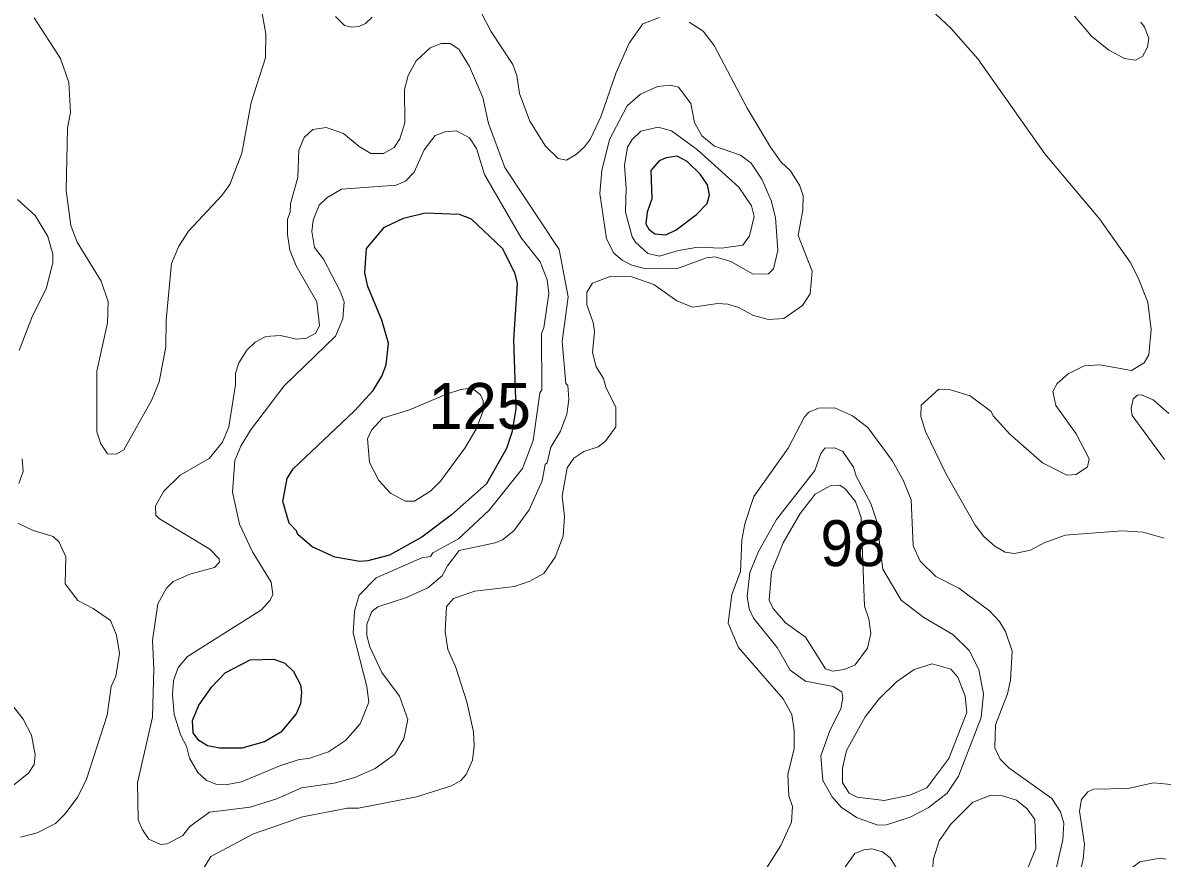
# Model space of a CAD drawing. Extents: x 673.6 to 698.9, y 7012 to 7040.1.
# Drawn here: x 688.765 to 690.749, y 7022.844 to 7024.299 of the extents above; entities that cross this region are included whole.
import ezdxf

# ---------------------------------------------------------------- set-up
doc = ezdxf.new("R2010")
doc.units = 0
doc.header["$LTSCALE"] = 0.032
doc.layers.add('1', color=7, linetype='Continuous', lineweight=25)
doc.layers.add('2', color=7, linetype='Continuous', lineweight=13)
doc.layers.add('21', color=7, linetype='Continuous')

msp = doc.modelspace()

# ---------------------------------------------------------------- linework, layer by layer
at = {"layer": '1'}
for points in [[(689.9221, 7024.0578), (689.9046, 7024.0666), (689.8854, 7024.0641), (689.8734, 7024.0589), (689.859, 7024.0419), (689.8603, 7023.9927), (689.8522, 7023.9692), (689.8499, 7023.9488), (689.8551, 7023.9395), (689.8655, 7023.9317), (689.885, 7023.9296), (689.9029, 7023.9383), (689.938, 7023.965), (689.9567, 7023.9845), (689.9607, 7023.9995), (689.9575, 7024.0169), (689.9444, 7024.0353)], [(689.6234, 7023.6258), (689.6166, 7023.5856), (689.6073, 7023.5576), (689.5728, 7023.4958), (689.5119, 7023.4422), (689.46, 7023.4028), (689.4039, 7023.3716), (689.3657, 7023.3616), (689.3522, 7023.3609), (689.3082, 7023.3682), (689.2689, 7023.386), (689.2442, 7023.4074), (689.2419, 7023.4139), (689.2292, 7023.4277), (689.2179, 7023.4651), (689.2252, 7023.5054), (689.2362, 7023.522), (689.343, 7023.6231), (689.375, 7023.6583), (689.3902, 7023.6834), (689.3978, 7023.7034), (689.4019, 7023.7413), (689.3903, 7023.781), (689.3659, 7023.8395), (689.3608, 7023.8637), (689.3636, 7023.9058), (689.3948, 7023.9434), (689.4282, 7023.9589), (689.466, 7023.968), (689.5252, 7023.9655), (689.5457, 7023.9575), (689.5999, 7023.9063), (689.6212, 7023.8644), (689.6262, 7023.8447), (689.6197, 7023.747)], [(689.2502, 7023.1332), (689.2488, 7023.1126), (689.2414, 7023.095), (689.2145, 7023.0633), (689.1862, 7023.0467), (689.1467, 7023.0353), (689.1081, 7023.0353), (689.0867, 7023.0394), (689.0716, 7023.0485), (689.0617, 7023.062), (689.0605, 7023.0839), (689.0716, 7023.1101), (689.0943, 7023.1422), (689.1176, 7023.1667), (689.1611, 7023.1895), (689.2021, 7023.1906), (689.2214, 7023.1837), (689.2367, 7023.1692), (689.2488, 7023.1456)]]:
    msp.add_lwpolyline(points, close=True, dxfattribs=at)
at = {"layer": '2'}
for points in [[(688.7852, 7024.3077), (688.831, 7024.2372), (688.8455, 7024.1952), (688.8481, 7024.1428), (688.8432, 7024.1163), (688.8406, 7024.0069), (688.8487, 7023.9461), (688.8597, 7023.9167), (688.9014, 7023.8488), (688.9138, 7023.8132), (688.9128, 7023.7767), (688.8941, 7023.6922), (688.8941, 7023.5868), (688.9011, 7023.5658), (688.9126, 7023.5481), (688.9279, 7023.5474), (688.941, 7023.5549), (688.9894, 7023.6409), (689.0024, 7023.6735), (689.014, 7023.7347), (689.0149, 7023.7809), (689.024, 7023.8797), (689.0369, 7023.9102), (689.0535, 7023.9359), (689.1118, 7023.9983), (689.1254, 7024.0176), (689.1467, 7024.0722), (689.1628, 7024.1603), (689.1875, 7024.2382), (689.1882, 7024.2802), (689.1801, 7024.325)], [(689.3099, 7024.3099), (689.3255, 7024.2947), (689.3382, 7024.2913), (689.3503, 7024.2925), (689.362, 7024.2981), (689.3737, 7024.3088)], [(689.5646, 7024.3149), (689.5804, 7024.2848), (689.6187, 7024.2263), (689.6254, 7024.2076), (689.6302, 7024.1758), (689.6481, 7024.1279), (689.6751, 7024.0844), (689.6974, 7024.0625), (689.7117, 7024.0601), (689.7296, 7024.0701), (689.7435, 7024.0828), (689.7535, 7024.0972), (689.7716, 7024.1353), (689.7985, 7024.2128), (689.8209, 7024.2635), (689.8449, 7024.2973), (689.8739, 7024.3083)], [(690.7529, 7023.401), (690.7158, 7023.4115), (690.6793, 7023.4141), (690.5804, 7023.4067), (690.5435, 7023.3932), (690.5198, 7023.3806), (690.4919, 7023.3748), (690.4756, 7023.3771), (690.458, 7023.3872), (690.4389, 7023.4042), (690.4235, 7023.4237), (690.3725, 7023.5141), (690.3368, 7023.5874), (690.3289, 7023.6131), (690.3293, 7023.6331), (690.3601, 7023.6606), (690.3805, 7023.66), (690.4146, 7023.649), (690.4514, 7023.6218), (690.4549, 7023.6143), (690.4838, 7023.5822), (690.5409, 7023.5327), (690.5833, 7023.5113), (690.5993, 7023.5121), (690.619, 7023.5254), (690.6222, 7023.5393), (690.5996, 7023.5828), (690.5639, 7023.6323), (690.559, 7023.6567), (690.5666, 7023.6707), (690.5852, 7023.6877), (690.6132, 7023.7017), (690.6408, 7023.7035), (690.6958, 7023.6936), (690.7181, 7023.7066), (690.7258, 7023.7206), (690.7298, 7023.7646), (690.7241, 7023.8123), (690.7076, 7023.8546), (690.6932, 7023.8819), (690.6402, 7023.9579), (690.5449, 7024.0709), (690.428, 7024.2362), (690.3814, 7024.2901), (690.3472, 7024.3219)], [(690.5967, 7024.3106), (690.626, 7024.2756), (690.6561, 7024.2517), (690.6833, 7024.2371), (690.7027, 7024.2343), (690.7152, 7024.2405), (690.7234, 7024.2568), (690.7257, 7024.2725), (690.7183, 7024.2917), (690.7118, 7024.3)], [(689.9256, 7024.3003), (689.95, 7024.2843), (689.9691, 7024.2597), (690.0266, 7024.1502), (690.0669, 7024.0824), (690.0859, 7024.0565), (690.1019, 7024.041), (690.1181, 7024.0153), (690.1241, 7023.9975)], [(689.5877, 7023.3929), (689.6004, 7023.3985), (689.6202, 7023.4139), (689.6466, 7023.4506), (689.6697, 7023.5009), (689.6748, 7023.5295), (689.678, 7023.5327), (689.6848, 7023.56), (689.7015, 7023.5877), (689.7124, 7023.6176), (689.7158, 7023.643), (689.7141, 7023.6674), (689.711, 7023.6709), (689.7042, 7023.7439), (689.7148, 7023.822), (689.6992, 7023.9042), (689.6046, 7024.0473), (689.5763, 7024.1238), (689.5661, 7024.1688), (689.5429, 7024.2233), (689.5243, 7024.2531), (689.5092, 7024.263), (689.4939, 7024.2632), (689.4745, 7024.2557), (689.4499, 7024.2328), (689.4361, 7024.2073), (689.4299, 7024.1827), (689.4305, 7024.1251), (689.4219, 7024.0969), (689.412, 7024.0817), (689.3931, 7024.0714), (689.3714, 7024.0714), (689.351, 7024.0834), (689.3235, 7024.1062), (689.2935, 7024.1167), (689.2699, 7024.1133), (689.2549, 7024.0996), (689.2459, 7024.0772), (689.2442, 7024.0295), (689.231, 7023.9844), (689.2309, 7023.9692), (689.2261, 7023.9568), (689.2261, 7023.9302), (689.2303, 7023.9031), (689.2409, 7023.876), (689.2769, 7023.813), (689.2816, 7023.772), (689.2752, 7023.7586), (689.2592, 7023.7496), (689.2425, 7023.7478), (689.2133, 7023.7543), (689.1884, 7023.7527), (689.1699, 7023.7426), (689.155, 7023.7287), (689.1415, 7023.7067), (689.1357, 7023.6886), (689.1356, 7023.6686), (689.1241, 7023.595), (689.1126, 7023.5686), (689.0898, 7023.5402), (689.0391, 7023.5113), (689.011, 7023.4834), (688.9963, 7023.4575), (688.9966, 7023.4414), (689.0029, 7023.4347), (689.0909, 7023.3819), (689.1072, 7023.3654), (689.1078, 7023.3594), (689.0989, 7023.3503), (689.0562, 7023.3383), (689.027, 7023.326), (689.0152, 7023.3141), (689.0003, 7023.2866), (688.9911, 7023.2229), (688.9934, 7023.1735), (688.991, 7023.0896), (688.9648, 7022.9753), (688.9662, 7022.9108), (688.9735, 7022.8929), (688.9846, 7022.8766), (689.0047, 7022.8675), (689.0167, 7022.8687), (689.0436, 7022.8833), (689.0562, 7022.8991), (689.0903, 7022.9242), (689.1608, 7022.9324), (689.2077, 7022.9473), (689.2504, 7022.9661), (689.3073, 7022.9747), (689.3434, 7022.9846), (689.3789, 7023), (689.4122, 7023.0245), (689.4285, 7023.0516), (689.4355, 7023.0851), (689.4209, 7023.1262)], [(688.7557, 7023.9912), (688.7866, 7023.9636), (688.8087, 7023.9266), (688.8176, 7023.8961), (688.8176, 7023.8809), (688.8056, 7023.8357), (688.7822, 7023.7885), (688.7586, 7023.7284)], [(690.1241, 7023.9975), (690.1235, 7023.9725), (690.1153, 7023.9286), (690.1397, 7023.8664), (690.1365, 7023.8269), (690.1231, 7023.8067)], [(690.1231, 7023.8067), (690.0905, 7023.784), (690.0639, 7023.7824), (690.0376, 7023.789), (690.0113, 7023.803), (689.9926, 7023.8092), (689.9756, 7023.8102), (689.9315, 7023.8037), (689.9039, 7023.8149), (689.8642, 7023.8433), (689.8255, 7023.8568), (689.7892, 7023.8578), (689.757, 7023.8455), (689.7472, 7023.8298), (689.7471, 7023.8078), (689.7585, 7023.777), (689.7609, 7023.7613), (689.757, 7023.7248), (689.7636, 7023.6998), (689.7765, 7023.6792), (689.7812, 7023.6629), (689.798, 7023.6295), (689.798, 7023.5953), (689.7797, 7023.5703), (689.7669, 7023.5605), (689.7422, 7023.5522), (689.7249, 7023.5409), (689.713, 7023.5241), (689.7044, 7023.4744), (689.7084, 7023.4392), (689.7059, 7023.4047), (689.692, 7023.368), (689.6726, 7023.3398), (689.6481, 7023.3261), (689.6215, 7023.317), (689.5525, 7023.3088), (689.5149, 7023.2963), (689.5029, 7023.282), (689.5006, 7023.2388), (689.5054, 7023.2074), (689.5185, 7023.1778), (689.5385, 7023.116), (689.5498, 7023.0638), (689.5513, 7023.0388), (689.5481, 7023.0148), (689.5372, 7022.9895), (689.528, 7022.9792), (689.5116, 7022.9696), (689.4506, 7022.9505), (689.3496, 7022.931), (689.3303, 7022.931), (689.252, 7022.916), (689.1666, 7022.8864), (689.0927, 7022.8467), (689.0782, 7022.8229)], [(690.7605, 7023.6186), (690.7333, 7023.6421), (690.7131, 7023.6508), (690.7064, 7023.6507), (690.6986, 7023.6441), (690.6954, 7023.6271), (690.6972, 7023.615), (690.7533, 7023.5385)], [(690.5517, 7022.7703), (690.576, 7022.876), (690.5777, 7022.9049), (690.5719, 7022.9247), (690.5571, 7022.9476), (690.482, 7023.0012), (690.4671, 7023.0162), (690.458, 7023.0358), (690.4588, 7023.076), (690.4799, 7023.1299), (690.485, 7023.1537), (690.4881, 7023.2042), (690.4765, 7023.2388), (690.4661, 7023.2563), (690.4485, 7023.2747), (690.3952, 7023.3143), (690.3549, 7023.3347), (690.3275, 7023.3613), (690.3158, 7023.3882), (690.3119, 7023.4681), (690.2986, 7023.5009), (690.2791, 7023.5365), (690.2364, 7023.5943), (690.2102, 7023.6142), (690.1784, 7023.6284), (690.151, 7023.6278), (690.134, 7023.6209), (690.1266, 7023.6129), (690.0981, 7023.5582), (690.0383, 7023.4739), (690.0224, 7023.426), (690.0172, 7023.3982), (690.0149, 7023.3435), (689.9999, 7023.303), (689.9936, 7023.2534), (690.0115, 7023.2106), (690.0891, 7023.1213), (690.1041, 7023.0942), (690.1086, 7023.0661), (690.1086, 7023.0348), (690.1041, 7023.0178), (690.0972, 7022.9898), (690.0988, 7022.9524), (690.1053, 7022.9339), (690.1038, 7022.9067), (690.0852, 7022.8659), (690.0588, 7022.8248)], [(688.7642, 7023.5394), (688.7658, 7023.5172), (688.7582, 7023.4964)], [(688.7564, 7023.4272), (688.7832, 7023.4145), (688.8182, 7023.4043), (688.8283, 7023.3944), (688.8398, 7023.3686), (688.8391, 7023.3219), (688.8612, 7023.2927), (688.8879, 7023.279), (688.9179, 7023.2577), (688.9284, 7023.2321), (688.9335, 7023.2002), (688.9269, 7023.1606), (688.9188, 7023.1426), (688.9123, 7023.0928), (688.8759, 7022.9816), (688.8609, 7022.9504), (688.8388, 7022.9209), (688.8221, 7022.9042), (688.7902, 7022.8881), (688.7613, 7022.8801)], [(689.3731, 7023.2733), (689.3833, 7023.2818), (689.4331, 7023.298), (689.4707, 7023.3146), (689.4951, 7023.3357), (689.5045, 7023.3531), (689.5252, 7023.3796), (689.5877, 7023.3929)], [(689.4209, 7023.1262), (689.3906, 7023.1673), (689.3692, 7023.2117), (689.3642, 7023.2318), (689.3641, 7023.2516), (689.3731, 7023.2733)], [(688.7379, 7022.9624), (688.7752, 7022.9921), (688.7848, 7023.0072), (688.7864, 7023.0237), (688.7803, 7023.0581), (688.7656, 7023.0857), (688.7435, 7023.1144)], [(690.7561, 7022.8422), (690.7456, 7022.8437), (690.7102, 7022.8372), (690.6861, 7022.819), (690.6409, 7022.7689), (690.6263, 7022.7626), (690.6168, 7022.7626), (690.6081, 7022.7668), (690.6017, 7022.775), (690.6, 7022.792), (690.6115, 7022.8423), (690.6139, 7022.8682), (690.605, 7022.9257), (690.6089, 7022.946), (690.6197, 7022.9596), (690.6297, 7022.9638), (690.6893, 7022.9653), (690.7341, 7022.9753), (690.7831, 7022.9703)], [(690.1813, 7022.8066), (690.2141, 7022.8521), (690.2299, 7022.8585), (690.2434, 7022.8601), (690.2621, 7022.8548), (690.2756, 7022.8444), (690.2951, 7022.8126)]]:
    msp.add_lwpolyline(points, dxfattribs=at)
for points in [[(690.015, 7024.0685), (690.0334, 7024.0547), (690.0521, 7024.0267), (690.0682, 7023.9896), (690.0757, 7023.9598), (690.0797, 7023.9023), (690.0724, 7023.8708), (690.0636, 7023.8618), (690.0372, 7023.8611), (689.9982, 7023.8831), (689.9705, 7023.8916), (689.9558, 7023.8899), (689.9036, 7023.8703), (689.8477, 7023.871), (689.8259, 7023.8767), (689.8089, 7023.8854), (689.7943, 7023.8976), (689.7813, 7023.9225), (689.7701, 7024.0018), (689.7733, 7024.0416), (689.7869, 7024.0956), (689.8175, 7024.1543), (689.8407, 7024.1751), (689.8703, 7024.1881), (689.8927, 7024.1907), (689.9071, 7024.1873), (689.9285, 7024.1585), (689.9346, 7024.1255), (689.9476, 7024.102), (689.9695, 7024.0845)], [(689.6538, 7023.5717), (689.6351, 7023.5225), (689.5775, 7023.4501), (689.5236, 7023.4002), (689.4792, 7023.3755), (689.4751, 7023.3692), (689.4602, 7023.3672), (689.3806, 7023.3319), (689.3511, 7023.3021), (689.3428, 7023.2741), (689.3403, 7023.2355), (689.3641, 7023.1429), (689.3674, 7023.1154), (689.3528, 7023.0776), (689.3273, 7023.0486), (689.2972, 7023.0291), (689.2634, 7023.0172), (689.2464, 7023.0157), (689.2126, 7023.0048), (689.1461, 7022.9767), (689.1215, 7022.9721), (689.1015, 7022.9728), (689.0844, 7022.9799), (689.0698, 7022.9932), (689.0553, 7023.0178), (689.0503, 7023.039), (689.0403, 7023.0576), (689.0286, 7023.0943), (689.0256, 7023.1287), (689.0273, 7023.1533), (689.0357, 7023.1761), (689.0521, 7023.195), (689.1807, 7023.2762), (689.1959, 7023.2935), (689.2003, 7023.3032), (689.1978, 7023.3244), (689.1654, 7023.3777), (689.1422, 7023.4259), (689.13, 7023.4816), (689.1343, 7023.5364), (689.1446, 7023.5616), (689.1617, 7023.5897), (689.2203, 7023.6665), (689.3097, 7023.7535), (689.3227, 7023.7833), (689.3247, 7023.813), (689.318, 7023.8319), (689.2887, 7023.8872), (689.2731, 7023.9074), (689.2684, 7023.9356), (689.2707, 7023.9555), (689.2814, 7023.9812), (689.2944, 7023.9944), (689.32, 7024.0091), (689.415, 7024.0165), (689.4317, 7024.0235), (689.4464, 7024.0389), (689.4641, 7024.0776), (689.4832, 7024.1031), (689.5005, 7024.1093), (689.5205, 7024.111), (689.5432, 7024.0986), (689.5552, 7024.0804), (689.5691, 7024.0348), (689.633, 7023.9246), (689.6658, 7023.883), (689.678, 7023.8513), (689.6813, 7023.8276), (689.6722, 7023.7676), (689.6682, 7023.7576), (689.669, 7023.6598), (689.6656, 7023.6538)], [(690.0342, 7023.9802), (690.0121, 7024.0127), (689.9403, 7024.0778), (689.8949, 7024.111), (689.8716, 7024.1175), (689.8415, 7024.1104), (689.8262, 7024.0956), (689.8182, 7024.0824), (689.8129, 7024.0506), (689.816, 7024.0115), (689.8146, 7023.9695), (689.8263, 7023.9263), (689.832, 7023.9168), (689.8537, 7023.8971), (689.8738, 7023.8926), (689.9068, 7023.9023), (689.9407, 7023.908), (689.9816, 7023.9064), (690.0187, 7023.912), (690.0303, 7023.9282), (690.0386, 7023.9618)], [(689.5669, 7023.6231), (689.5548, 7023.5911), (689.5348, 7023.558), (689.4922, 7023.5007), (689.4754, 7023.4837), (689.4475, 7023.466), (689.4312, 7023.466), (689.4057, 7023.4794), (689.3853, 7023.5019), (689.3688, 7023.5331), (689.3652, 7023.5743), (689.3726, 7023.5895), (689.3912, 7023.6104), (689.4387, 7023.6248), (689.5028, 7023.6519), (689.5278, 7023.6605), (689.5409, 7023.6622), (689.5513, 7023.6598), (689.5619, 7023.6508), (689.5669, 7023.6403)], [(690.2629, 7023.3471), (690.2949, 7023.293), (690.3344, 7023.2631), (690.3847, 7023.2333), (690.4133, 7023.2053), (690.4299, 7023.1725), (690.4382, 7023.1299), (690.434, 7023.0888), (690.3946, 7022.9869), (690.3748, 7022.9573), (690.3419, 7022.9317), (690.3101, 7022.915), (690.2689, 7022.9019), (690.2543, 7022.9013), (690.2168, 7022.9147), (690.1901, 7022.9326), (690.1743, 7022.9506), (690.158, 7022.9789), (690.1547, 7023.0223), (690.1712, 7023.0676), (690.1894, 7023.1042), (690.1932, 7023.1229), (690.1913, 7023.1333), (690.1765, 7023.143), (690.1278, 7023.1524), (690.1013, 7023.1716), (690.0786, 7023.2109), (690.0373, 7023.262), (690.0301, 7023.2783), (690.0266, 7023.2998), (690.0313, 7023.3415), (690.0462, 7023.3781), (690.0775, 7023.4336), (690.1445, 7023.519), (690.1547, 7023.5489), (690.1619, 7023.5581), (690.1786, 7023.5588), (690.193, 7023.5523), (690.2118, 7023.5251), (690.2162, 7023.5094), (690.2417, 7023.4617), (690.2525, 7023.4303)], [(690.2309, 7023.2829), (690.2383, 7023.2606), (690.2417, 7023.2354), (690.2362, 7023.2099), (690.2144, 7023.1807), (690.1954, 7023.1725), (690.1754, 7023.1694), (690.1628, 7023.1736), (690.128, 7023.2287), (690.093, 7023.2539), (690.0715, 7023.2788), (690.0651, 7023.2933), (690.0689, 7023.3424), (690.0893, 7023.3929), (690.1188, 7023.4443), (690.1448, 7023.4781), (690.171, 7023.4922), (690.1877, 7023.4936), (690.1969, 7023.4875), (690.2152, 7023.4654), (690.2253, 7023.4371)], [(690.2864, 7023.151), (690.3173, 7023.1725), (690.3485, 7023.1823), (690.3813, 7023.1732), (690.3933, 7023.1594), (690.4062, 7023.1262), (690.4093, 7023.0973), (690.3777, 7023.0173), (690.3395, 7022.9664), (690.3095, 7022.9533), (690.2651, 7022.9442), (690.218, 7022.9501), (690.2043, 7022.9569), (690.1925, 7022.975), (690.1925, 7023.0004), (690.1992, 7023.0316), (690.232, 7023.09), (690.2563, 7023.1213)], [(690.3811, 7022.9031), (690.4195, 7022.9414), (690.4494, 7022.953), (690.4709, 7022.9522), (690.4954, 7022.9446), (690.5139, 7022.9299), (690.5276, 7022.9112), (690.5292, 7022.8604), (690.5098, 7022.814), (690.475, 7022.7564), (690.4645, 7022.7304), (690.4505, 7022.6782), (690.4339, 7022.6524), (690.4161, 7022.6516), (690.4024, 7022.6625), (690.3834, 7022.7256), (690.3599, 7022.757), (690.3512, 7022.7761), (690.3477, 7022.8033), (690.3511, 7022.8426), (690.361, 7022.8738)]]:
    msp.add_lwpolyline(points, close=True, dxfattribs=at)

# ---------------------------------------------------------------- texts
at = {"layer": '21'}
msp.add_text('125', height=0.08, dxfattribs=at).set_placement((689.4715, 7023.5916))
at = {"layer": '21', "width": 0.95}
msp.add_text('98', height=0.08, dxfattribs=at).set_placement((690.1542, 7023.3526))

doc.saveas('drawing.dxf')
